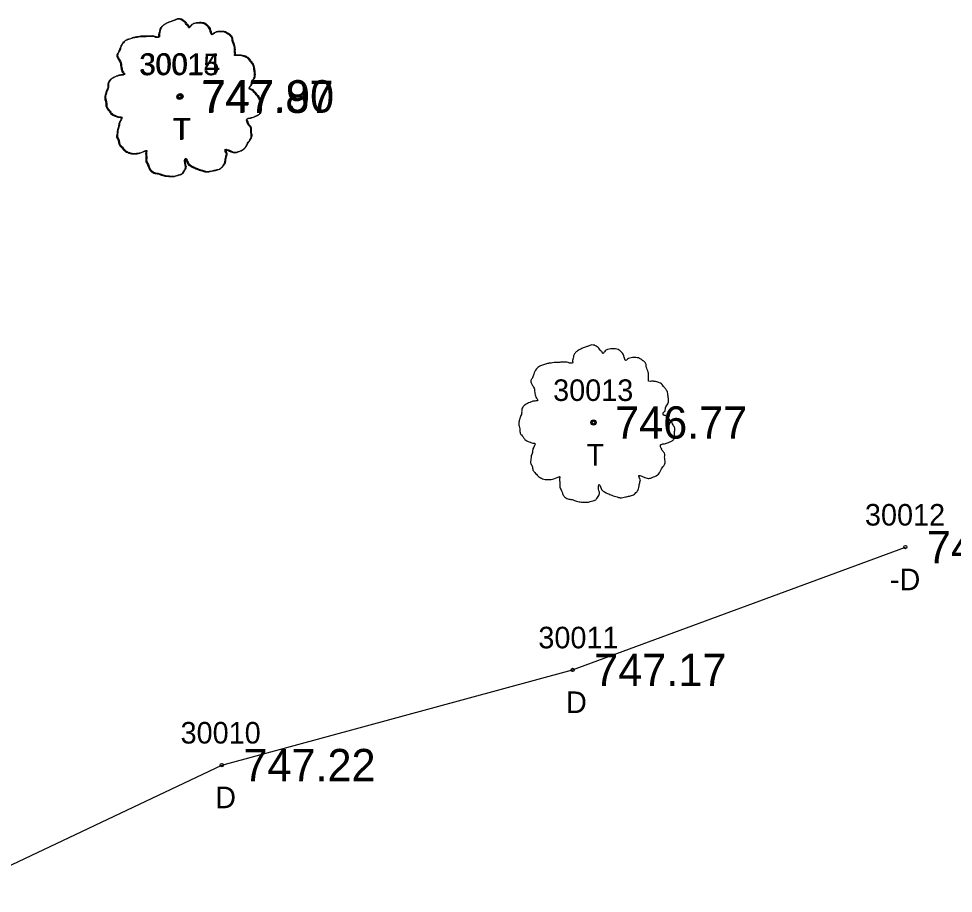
# Model space of a CAD drawing. Extents: x 1375131 to 1378678, y 999028 to 1004053.
# Drawn here: x 1376765.86 to 1376809.22, y 1002931.35 to 1002971.93 of the extents above; entities that cross this region are included whole.
import ezdxf

# ---------------------------------------------------------------- set-up
doc = ezdxf.new("R2010")
doc.units = 0
for name, color, linetype in [('RD_EX_Driveway', 7, 'Continuous'), ('RD_EX_Driveway_txCode', 7, 'Continuous'), ('RD_EX_TX_Driveway_ELEV', 7, 'Continuous'), ('RD_EX_TX_VEG_ELEV', 7, 'Continuous'), ('RD_EX_VEG', 7, 'Continuous'), ('RD_EX_VEG_txCode', 7, 'Continuous'), ('RD_SMD_Locator', 7, 'Continuous')]:
    doc.layers.add(name, color=color, linetype=linetype)

msp = doc.modelspace()

# ---------------------------------------------------------------- linework, layer by layer
at = {"layer": 'RD_EX_Driveway'}
msp.add_lwpolyline([(1376706.507, 1002954.761), (1376715.388, 1002940.545), (1376723.048, 1002920.461), (1376726.876, 1002920.427), (1376736.336, 1002921.326), (1376751.407, 1002925.999), (1376775.28, 1002937.302), (1376791.557, 1002941.719), (1376806.993, 1002947.414)], dxfattribs=at)
at = {"layer": 'RD_EX_VEG'}
for centre, radius in [((1376773.321, 1002968.304), 0.125), ((1376773.357, 1002968.327), 0.125), ((1376773.315, 1002968.295), 0.00005), ((1376773.351, 1002968.318), 0.00005), ((1376792.526, 1002953.195), 0.125), ((1376792.52, 1002953.186), 0.00005)]:
    msp.add_circle(centre, radius, dxfattribs=at)
for points in [[(1376773.387, 1002971.888), (1376773.237, 1002971.9), (1376773.075, 1002971.85), (1376772.95, 1002971.8), (1376772.837, 1002971.763), (1376772.725, 1002971.713), (1376772.575, 1002971.625), (1376772.462, 1002971.525), (1376772.4, 1002971.4), (1376772.375, 1002971.288), (1376772.35, 1002971.15), (1376772.35, 1002971.063), (1376772.287, 1002971.05), (1376772.212, 1002971.063), (1376772.088, 1002971.1), (1376771.963, 1002971.1), (1376771.838, 1002971.1), (1376771.663, 1002971.088), (1376771.488, 1002971.088), (1376771.35, 1002971.063), (1376771.188, 1002971.038), (1376771.001, 1002970.976), (1376770.826, 1002970.913), (1376770.676, 1002970.788), (1376770.551, 1002970.551), (1376770.488, 1002970.376), (1376770.413, 1002970.251), (1376770.488, 1002970.026), (1376770.576, 1002969.851), (1376770.588, 1002969.751), (1376770.626, 1002969.539), (1376770.676, 1002969.426), (1376770.738, 1002969.326), (1376770.701, 1002969.314), (1376770.513, 1002969.289), (1376770.363, 1002969.239), (1376770.151, 1002969.126), (1376770.038, 1002969.014), (1376769.988, 1002968.851), (1376769.976, 1002968.677), (1376769.926, 1002968.577), (1376769.889, 1002968.439), (1376769.876, 1002968.402), (1376769.851, 1002968.239), (1376769.901, 1002968.014), (1376769.914, 1002967.839), (1376769.976, 1002967.727), (1376770.051, 1002967.64), (1376770.138, 1002967.515), (1376770.338, 1002967.402), (1376770.501, 1002967.352), (1376770.601, 1002967.34), (1376770.513, 1002967.09), (1376770.488, 1002966.915), (1376770.426, 1002966.715), (1376770.426, 1002966.677), (1376770.401, 1002966.44), (1376770.476, 1002966.278), (1376770.513, 1002966.09), (1376770.601, 1002965.978), (1376770.738, 1002965.828), (1376770.901, 1002965.715), (1376771.15, 1002965.653), (1376771.35, 1002965.665), (1376771.638, 1002965.753), (1376771.763, 1002965.79), (1376771.75, 1002965.703), (1376771.763, 1002965.515), (1376771.763, 1002965.303), (1376771.838, 1002965.141), (1376771.888, 1002965.003), (1376771.963, 1002964.878), (1376772.125, 1002964.766), (1376772.325, 1002964.728), (1376772.537, 1002964.653), (1376772.762, 1002964.616), (1376773.012, 1002964.603), (1376773.312, 1002964.678), (1376773.449, 1002964.741), (1376773.499, 1002964.828), (1376773.599, 1002965.016), (1376773.574, 1002965.128), (1376773.587, 1002965.428), (1376773.637, 1002965.34), (1376773.724, 1002965.166), (1376773.974, 1002965.016), (1376774.174, 1002964.928), (1376774.412, 1002964.853), (1376774.561, 1002964.816), (1376774.799, 1002964.853), (1376774.986, 1002964.891), (1376775.174, 1002964.953), (1376775.324, 1002965.091), (1376775.411, 1002965.228), (1376775.436, 1002965.365), (1376775.474, 1002965.553), (1376775.499, 1002965.64)], [(1376773.423, 1002971.911), (1376773.273, 1002971.923), (1376773.111, 1002971.873), (1376772.986, 1002971.823), (1376772.873, 1002971.786), (1376772.761, 1002971.736), (1376772.611, 1002971.648), (1376772.498, 1002971.548), (1376772.436, 1002971.423), (1376772.411, 1002971.311), (1376772.386, 1002971.173), (1376772.386, 1002971.086), (1376772.323, 1002971.073), (1376772.248, 1002971.086), (1376772.124, 1002971.123), (1376771.999, 1002971.123), (1376771.874, 1002971.123), (1376771.699, 1002971.111), (1376771.524, 1002971.111), (1376771.386, 1002971.086), (1376771.224, 1002971.061), (1376771.037, 1002970.999), (1376770.862, 1002970.936), (1376770.712, 1002970.811), (1376770.587, 1002970.574), (1376770.524, 1002970.399), (1376770.449, 1002970.274), (1376770.524, 1002970.049), (1376770.612, 1002969.874), (1376770.624, 1002969.774), (1376770.662, 1002969.562), (1376770.712, 1002969.449), (1376770.774, 1002969.349), (1376770.737, 1002969.337), (1376770.549, 1002969.312), (1376770.399, 1002969.262), (1376770.187, 1002969.149), (1376770.074, 1002969.037), (1376770.024, 1002968.874), (1376770.012, 1002968.7), (1376769.962, 1002968.6), (1376769.925, 1002968.462), (1376769.912, 1002968.425), (1376769.887, 1002968.262), (1376769.937, 1002968.037), (1376769.95, 1002967.862), (1376770.012, 1002967.75), (1376770.087, 1002967.663), (1376770.174, 1002967.538), (1376770.374, 1002967.425), (1376770.537, 1002967.375), (1376770.637, 1002967.363), (1376770.549, 1002967.113), (1376770.524, 1002966.938), (1376770.462, 1002966.738), (1376770.462, 1002966.7), (1376770.437, 1002966.463), (1376770.512, 1002966.301), (1376770.549, 1002966.113), (1376770.637, 1002966.001), (1376770.774, 1002965.851), (1376770.937, 1002965.738), (1376771.186, 1002965.676), (1376771.386, 1002965.688), (1376771.674, 1002965.776), (1376771.799, 1002965.813), (1376771.786, 1002965.726), (1376771.799, 1002965.538), (1376771.799, 1002965.326), (1376771.874, 1002965.164), (1376771.924, 1002965.026), (1376771.999, 1002964.901), (1376772.161, 1002964.789), (1376772.361, 1002964.751), (1376772.573, 1002964.676), (1376772.798, 1002964.639), (1376773.048, 1002964.626), (1376773.348, 1002964.701), (1376773.485, 1002964.764), (1376773.535, 1002964.851), (1376773.635, 1002965.039), (1376773.61, 1002965.151), (1376773.623, 1002965.451), (1376773.673, 1002965.363), (1376773.76, 1002965.189), (1376774.01, 1002965.039), (1376774.21, 1002964.951), (1376774.448, 1002964.876), (1376774.597, 1002964.839), (1376774.835, 1002964.876), (1376775.022, 1002964.914), (1376775.21, 1002964.976), (1376775.36, 1002965.114), (1376775.447, 1002965.251), (1376775.472, 1002965.388), (1376775.51, 1002965.576), (1376775.535, 1002965.663)], [(1376775.499, 1002965.64), (1376775.461, 1002965.728), (1376775.436, 1002965.853), (1376775.474, 1002965.84), (1376775.561, 1002965.815), (1376775.698, 1002965.753), (1376775.811, 1002965.715), (1376775.973, 1002965.728), (1376776.111, 1002965.778), (1376776.336, 1002965.915), (1376776.473, 1002966.153), (1376776.611, 1002966.353), (1376776.648, 1002966.515), (1376776.623, 1002966.627), (1376776.611, 1002966.877), (1376776.511, 1002967.002), (1376776.486, 1002967.065), (1376776.436, 1002967.265), (1376776.473, 1002967.29), (1376776.611, 1002967.315), (1376776.798, 1002967.377), (1376776.935, 1002967.44), (1376777.048, 1002967.527), (1376777.085, 1002967.64), (1376777.073, 1002967.839), (1376777.098, 1002968.039), (1376777.06, 1002968.114), (1376777.01, 1002968.189), (1376776.973, 1002968.289), (1376776.898, 1002968.364), (1376776.848, 1002968.439), (1376776.798, 1002968.489), (1376776.736, 1002968.564), (1376776.648, 1002968.627), (1376776.573, 1002968.652), (1376776.548, 1002968.727), (1376776.623, 1002968.826), (1376776.648, 1002968.876), (1376776.661, 1002968.989), (1376776.773, 1002969.164), (1376776.798, 1002969.364), (1376776.773, 1002969.576), (1376776.748, 1002969.714), (1376776.673, 1002969.851), (1376776.573, 1002969.976), (1376776.511, 1002970.063), (1376776.423, 1002970.126), (1376776.261, 1002970.188), (1376776.136, 1002970.213), (1376775.961, 1002970.213), (1376775.861, 1002970.238), (1376775.873, 1002970.263), (1376775.873, 1002970.338), (1376775.873, 1002970.476), (1376775.836, 1002970.701), (1376775.761, 1002970.951), (1376775.761, 1002970.963), (1376775.711, 1002971.088), (1376775.599, 1002971.188), (1376775.511, 1002971.238), (1376775.411, 1002971.3), (1376775.286, 1002971.313), (1376775.136, 1002971.313), (1376774.999, 1002971.288), (1376774.899, 1002971.238), (1376774.811, 1002971.175), (1376774.774, 1002971.25), (1376774.724, 1002971.4), (1376774.699, 1002971.475), (1376774.624, 1002971.563), (1376774.512, 1002971.663), (1376774.287, 1002971.725), (1376773.974, 1002971.688), (1376773.824, 1002971.588), (1376773.749, 1002971.5), (1376773.724, 1002971.563), (1376773.624, 1002971.663), (1376773.574, 1002971.75), (1376773.487, 1002971.813), (1376773.412, 1002971.863), (1376773.362, 1002971.888)], [(1376775.535, 1002965.663), (1376775.497, 1002965.751), (1376775.472, 1002965.876), (1376775.51, 1002965.863), (1376775.597, 1002965.838), (1376775.734, 1002965.776), (1376775.847, 1002965.738), (1376776.009, 1002965.751), (1376776.147, 1002965.801), (1376776.372, 1002965.938), (1376776.509, 1002966.176), (1376776.647, 1002966.376), (1376776.684, 1002966.538), (1376776.659, 1002966.65), (1376776.647, 1002966.9), (1376776.547, 1002967.025), (1376776.522, 1002967.088), (1376776.472, 1002967.288), (1376776.509, 1002967.313), (1376776.647, 1002967.338), (1376776.834, 1002967.4), (1376776.971, 1002967.463), (1376777.084, 1002967.55), (1376777.121, 1002967.663), (1376777.109, 1002967.862), (1376777.134, 1002968.062), (1376777.096, 1002968.137), (1376777.046, 1002968.212), (1376777.009, 1002968.312), (1376776.934, 1002968.387), (1376776.884, 1002968.462), (1376776.834, 1002968.512), (1376776.772, 1002968.587), (1376776.684, 1002968.65), (1376776.609, 1002968.675), (1376776.584, 1002968.75), (1376776.659, 1002968.849), (1376776.684, 1002968.899), (1376776.697, 1002969.012), (1376776.809, 1002969.187), (1376776.834, 1002969.387), (1376776.809, 1002969.599), (1376776.784, 1002969.737), (1376776.709, 1002969.874), (1376776.609, 1002969.999), (1376776.547, 1002970.086), (1376776.459, 1002970.149), (1376776.297, 1002970.211), (1376776.172, 1002970.236), (1376775.997, 1002970.236), (1376775.897, 1002970.261), (1376775.909, 1002970.286), (1376775.909, 1002970.361), (1376775.909, 1002970.499), (1376775.872, 1002970.724), (1376775.797, 1002970.974), (1376775.797, 1002970.986), (1376775.747, 1002971.111), (1376775.635, 1002971.211), (1376775.547, 1002971.261), (1376775.447, 1002971.323), (1376775.322, 1002971.336), (1376775.172, 1002971.336), (1376775.035, 1002971.311), (1376774.935, 1002971.261), (1376774.847, 1002971.198), (1376774.81, 1002971.273), (1376774.76, 1002971.423), (1376774.735, 1002971.498), (1376774.66, 1002971.586), (1376774.548, 1002971.686), (1376774.323, 1002971.748), (1376774.01, 1002971.711), (1376773.86, 1002971.611), (1376773.785, 1002971.523), (1376773.76, 1002971.586), (1376773.66, 1002971.686), (1376773.61, 1002971.773), (1376773.523, 1002971.836), (1376773.448, 1002971.886), (1376773.398, 1002971.911)], [(1376792.592, 1002956.779), (1376792.442, 1002956.791), (1376792.28, 1002956.741), (1376792.155, 1002956.691), (1376792.042, 1002956.654), (1376791.93, 1002956.604), (1376791.78, 1002956.516), (1376791.667, 1002956.416), (1376791.605, 1002956.291), (1376791.58, 1002956.179), (1376791.555, 1002956.041), (1376791.555, 1002955.954), (1376791.492, 1002955.941), (1376791.417, 1002955.954), (1376791.293, 1002955.991), (1376791.168, 1002955.991), (1376791.043, 1002955.991), (1376790.868, 1002955.979), (1376790.693, 1002955.979), (1376790.555, 1002955.954), (1376790.393, 1002955.929), (1376790.206, 1002955.867), (1376790.031, 1002955.804), (1376789.881, 1002955.679), (1376789.756, 1002955.442), (1376789.693, 1002955.267), (1376789.618, 1002955.142), (1376789.693, 1002954.917), (1376789.781, 1002954.742), (1376789.793, 1002954.642), (1376789.831, 1002954.43), (1376789.881, 1002954.317), (1376789.943, 1002954.217), (1376789.906, 1002954.205), (1376789.718, 1002954.18), (1376789.568, 1002954.13), (1376789.356, 1002954.017), (1376789.243, 1002953.905), (1376789.193, 1002953.742), (1376789.181, 1002953.568), (1376789.131, 1002953.468), (1376789.094, 1002953.33), (1376789.081, 1002953.293), (1376789.056, 1002953.13), (1376789.106, 1002952.905), (1376789.119, 1002952.73), (1376789.181, 1002952.618), (1376789.256, 1002952.531), (1376789.343, 1002952.406), (1376789.543, 1002952.293), (1376789.706, 1002952.243), (1376789.806, 1002952.231), (1376789.718, 1002951.981), (1376789.693, 1002951.806), (1376789.631, 1002951.606), (1376789.631, 1002951.568), (1376789.606, 1002951.331), (1376789.681, 1002951.169), (1376789.718, 1002950.981), (1376789.806, 1002950.869), (1376789.943, 1002950.719), (1376790.106, 1002950.606), (1376790.355, 1002950.544), (1376790.555, 1002950.556), (1376790.843, 1002950.644), (1376790.968, 1002950.681), (1376790.955, 1002950.594), (1376790.968, 1002950.406), (1376790.968, 1002950.194), (1376791.043, 1002950.032), (1376791.093, 1002949.894), (1376791.168, 1002949.769), (1376791.33, 1002949.657), (1376791.53, 1002949.619), (1376791.742, 1002949.544), (1376791.967, 1002949.507), (1376792.217, 1002949.494), (1376792.517, 1002949.569), (1376792.654, 1002949.632), (1376792.704, 1002949.719), (1376792.804, 1002949.907), (1376792.779, 1002950.019), (1376792.792, 1002950.319), (1376792.842, 1002950.231), (1376792.929, 1002950.057), (1376793.179, 1002949.907), (1376793.379, 1002949.819), (1376793.617, 1002949.744), (1376793.766, 1002949.707), (1376794.004, 1002949.744), (1376794.191, 1002949.782), (1376794.379, 1002949.844), (1376794.529, 1002949.982), (1376794.616, 1002950.119), (1376794.641, 1002950.256), (1376794.679, 1002950.444), (1376794.704, 1002950.531)], [(1376794.704, 1002950.531), (1376794.666, 1002950.619), (1376794.641, 1002950.744), (1376794.679, 1002950.731), (1376794.766, 1002950.706), (1376794.903, 1002950.644), (1376795.016, 1002950.606), (1376795.178, 1002950.619), (1376795.316, 1002950.669), (1376795.541, 1002950.806), (1376795.678, 1002951.044), (1376795.816, 1002951.244), (1376795.853, 1002951.406), (1376795.828, 1002951.518), (1376795.816, 1002951.768), (1376795.716, 1002951.893), (1376795.691, 1002951.956), (1376795.641, 1002952.156), (1376795.678, 1002952.181), (1376795.816, 1002952.206), (1376796.003, 1002952.268), (1376796.14, 1002952.331), (1376796.253, 1002952.418), (1376796.29, 1002952.531), (1376796.278, 1002952.73), (1376796.303, 1002952.93), (1376796.265, 1002953.005), (1376796.215, 1002953.08), (1376796.178, 1002953.18), (1376796.103, 1002953.255), (1376796.053, 1002953.33), (1376796.003, 1002953.38), (1376795.941, 1002953.455), (1376795.853, 1002953.518), (1376795.778, 1002953.543), (1376795.753, 1002953.618), (1376795.828, 1002953.717), (1376795.853, 1002953.767), (1376795.866, 1002953.88), (1376795.978, 1002954.055), (1376796.003, 1002954.255), (1376795.978, 1002954.467), (1376795.953, 1002954.605), (1376795.878, 1002954.742), (1376795.778, 1002954.867), (1376795.716, 1002954.954), (1376795.628, 1002955.017), (1376795.466, 1002955.079), (1376795.341, 1002955.104), (1376795.166, 1002955.104), (1376795.066, 1002955.129), (1376795.078, 1002955.154), (1376795.078, 1002955.229), (1376795.078, 1002955.367), (1376795.041, 1002955.592), (1376794.966, 1002955.842), (1376794.966, 1002955.854), (1376794.916, 1002955.979), (1376794.804, 1002956.079), (1376794.716, 1002956.129), (1376794.616, 1002956.191), (1376794.491, 1002956.204), (1376794.341, 1002956.204), (1376794.204, 1002956.179), (1376794.104, 1002956.129), (1376794.016, 1002956.066), (1376793.979, 1002956.141), (1376793.929, 1002956.291), (1376793.904, 1002956.366), (1376793.829, 1002956.454), (1376793.717, 1002956.554), (1376793.492, 1002956.616), (1376793.179, 1002956.579), (1376793.029, 1002956.479), (1376792.954, 1002956.391), (1376792.929, 1002956.454), (1376792.829, 1002956.554), (1376792.779, 1002956.641), (1376792.692, 1002956.704), (1376792.617, 1002956.754), (1376792.567, 1002956.779)]]:
    msp.add_spline(points, degree=3, dxfattribs=at)
at = {"layer": 'RD_SMD_Locator'}
for centre in [(1376773.321, 1002968.304), (1376773.357, 1002968.327), (1376792.526, 1002953.195), (1376806.993, 1002947.414), (1376791.557, 1002941.719), (1376775.28, 1002937.302)]:
    msp.add_circle(centre, 0.075, dxfattribs=at)

# ---------------------------------------------------------------- texts
at = {"layer": 'RD_EX_Driveway_txCode'}
for s, p in [('30012', (1376805.119, 1002948.414)), ('-D', (1376806.276, 1002945.414)), ('30011', (1376789.966, 1002942.719)), ('D', (1376791.25, 1002939.719)), ('30010', (1376773.367, 1002938.302)), ('D', (1376774.973, 1002935.302))]:
    msp.add_text(s, height=1, dxfattribs=at).set_placement(p)
at = {"layer": 'RD_EX_TX_Driveway_ELEV'}
for s, p in [('747.57', (1376807.993, 1002946.664)), ('747.17', (1376792.557, 1002940.969)), ('747.22', (1376776.28, 1002936.552))]:
    msp.add_text(s, height=1.5, dxfattribs=at).set_placement(p)
at = {"layer": 'RD_EX_TX_VEG_ELEV'}
for s, p in [('747.87', (1376774.321, 1002967.554)), ('747.90', (1376774.357, 1002967.577)), ('746.77', (1376793.526, 1002952.445))]:
    msp.add_text(s, height=1.5, dxfattribs=at).set_placement(p)
at = {"layer": 'RD_EX_VEG_txCode'}
for s, p in [('30015', (1376771.447, 1002969.304)), ('30014', (1376771.483, 1002969.327)), ('T', (1376772.998, 1002966.304)), ('T', (1376773.034, 1002966.327)), ('30013', (1376790.652, 1002954.195)), ('T', (1376792.203, 1002951.195))]:
    msp.add_text(s, height=1, dxfattribs=at).set_placement(p)

doc.saveas('drawing.dxf')
